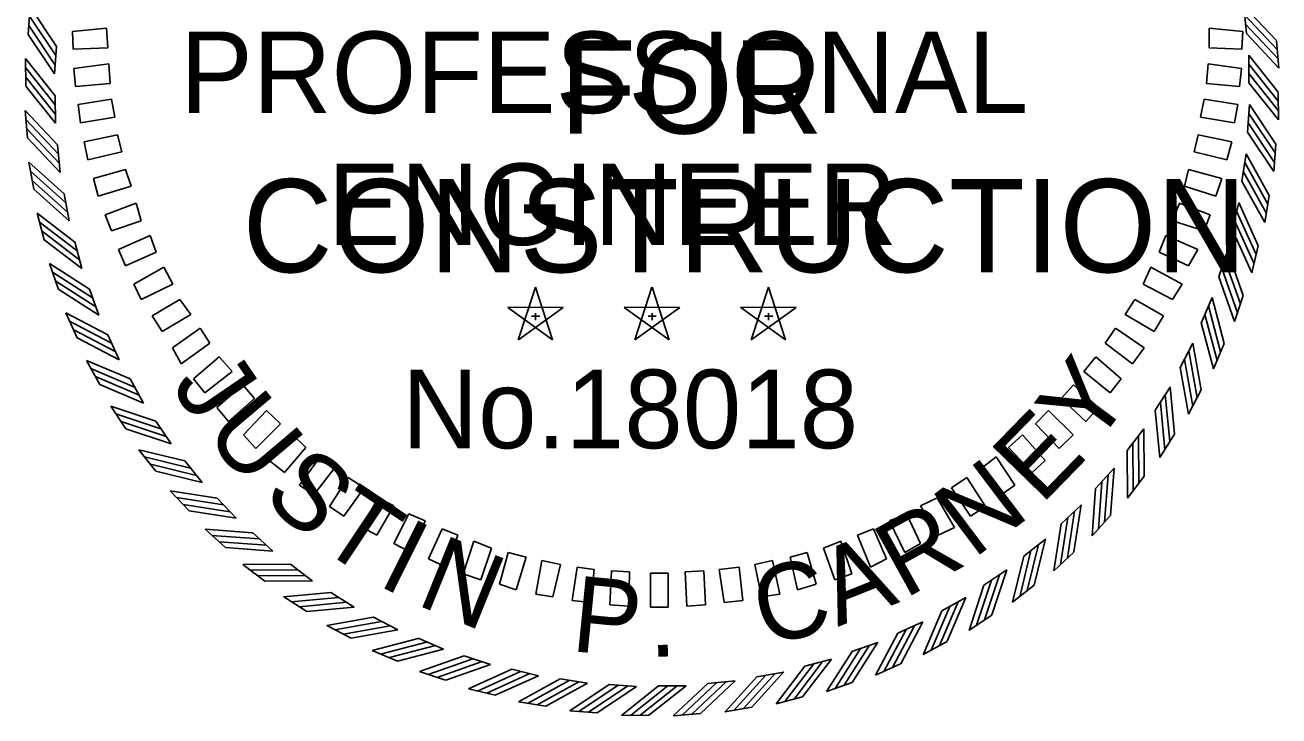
# Model space of a CAD drawing. Extents: x 16 to 1228743, y 11 to 152440.
# Drawn here: x 17.6793 to 17.8515, y 10.8149 to 10.9098 of the extents above; entities that cross this region are included whole.
import ezdxf

# ---------------------------------------------------------------- set-up
doc = ezdxf.new("R2010")
doc.units = 0
doc.layers.add('STAMP_JUSTIN', color=7, linetype='Continuous')
doc.layers.add('STAMP_PRELIM', color=7, linetype='Continuous')

msp = doc.modelspace()

# ---------------------------------------------------------------- linework, layer by layer
at = {"layer": 'STAMP_JUSTIN'}
for p, q in [((17.67974, 10.90855), (17.68001, 10.91231)), ((17.84664, 10.91243), (17.84699, 10.90866)), ((17.85111, 10.90767), (17.85146, 10.90392)), ((17.68336, 10.90312), (17.68364, 10.90689)), ((17.84731, 10.90568), (17.84734, 10.9019)), ((17.67941, 10.90145), (17.67937, 10.90522)), ((17.68347, 10.89634), (17.68343, 10.90012)), ((17.85137, 10.90057), (17.8514, 10.8968)), ((17.84741, 10.8989), (17.84714, 10.89513)), ((17.67966, 10.89435), (17.67932, 10.8981)), ((17.68413, 10.88959), (17.68378, 10.89335)), ((17.85104, 10.89347), (17.85076, 10.88971)), ((17.84696, 10.89213), (17.84637, 10.8884)), ((17.68051, 10.88729), (17.67985, 10.891)), ((17.68535, 10.88292), (17.6847, 10.88664)), ((17.85012, 10.88642), (17.84954, 10.8827)), ((17.84595, 10.88542), (17.84505, 10.88175)), ((17.68193, 10.88033), (17.68097, 10.88397)), ((17.68712, 10.87637), (17.68616, 10.88003)), ((17.84863, 10.87948), (17.84774, 10.87581)), ((17.84439, 10.87883), (17.84319, 10.87524)), ((17.68392, 10.87351), (17.68267, 10.87706)), ((17.68942, 10.86999), (17.68816, 10.87356)), ((17.74939, 10.87381), (17.74703, 10.86658)), ((17.75174, 10.86658), (17.74939, 10.87382)), ((17.76538, 10.87381), (17.76302, 10.86658)), ((17.76773, 10.86658), (17.76539, 10.87382)), ((17.78137, 10.87381), (17.77901, 10.86658)), ((17.78372, 10.86658), (17.78138, 10.87382)), ((17.84657, 10.87268), (17.84538, 10.8691)), ((17.75319, 10.87105), (17.74558, 10.87106)), ((17.74559, 10.87105), (17.75174, 10.86657)), ((17.74704, 10.86658), (17.7532, 10.87105)), ((17.76918, 10.87105), (17.76157, 10.87106)), ((17.76158, 10.87105), (17.76773, 10.86657)), ((17.76303, 10.86658), (17.76919, 10.87105)), ((17.78517, 10.87105), (17.77756, 10.87106)), ((17.77757, 10.87105), (17.78372, 10.86657)), ((17.77902, 10.86658), (17.78518, 10.87105)), ((17.84228, 10.87238), (17.8408, 10.8689)), ((17.68647, 10.86687), (17.68493, 10.87031)), ((17.74885, 10.86983), (17.74998, 10.86983)), ((17.7494, 10.87024), (17.7494, 10.86928)), ((17.76484, 10.86983), (17.76597, 10.86983)), ((17.76539, 10.87024), (17.76539, 10.86928)), ((17.78083, 10.86983), (17.78196, 10.86983)), ((17.78138, 10.87024), (17.78138, 10.86928)), ((17.69224, 10.86383), (17.69069, 10.86727)), ((17.83966, 10.86613), (17.83789, 10.86279)), ((17.84395, 10.86607), (17.84247, 10.8626)), ((17.68956, 10.86047), (17.68774, 10.86377)), ((17.69556, 10.85791), (17.69373, 10.86122)), ((17.83652, 10.86011), (17.83449, 10.85693)), ((17.8408, 10.8597), (17.83903, 10.85637)), ((17.69317, 10.85435), (17.69108, 10.85749)), ((17.69936, 10.85229), (17.69726, 10.85544)), ((17.8329, 10.85438), (17.83061, 10.85137)), ((17.83713, 10.85362), (17.83509, 10.85044)), ((17.69727, 10.84855), (17.69492, 10.8515)), ((17.70361, 10.84701), (17.70126, 10.84997)), ((17.82882, 10.84896), (17.82629, 10.84616)), ((17.83297, 10.84785), (17.83068, 10.84486)), ((17.70183, 10.8431), (17.69925, 10.84585)), ((17.70828, 10.84209), (17.70569, 10.84485)), ((17.82431, 10.8439), (17.82155, 10.84132)), ((17.82835, 10.84245), (17.82582, 10.83966)), ((17.70683, 10.83805), (17.70403, 10.84058)), ((17.71334, 10.83758), (17.71054, 10.84011)), ((17.81939, 10.83923), (17.81643, 10.83688)), ((17.8233, 10.83745), (17.82055, 10.83488)), ((17.71223, 10.83343), (17.70923, 10.83572)), ((17.71875, 10.83349), (17.71575, 10.83579)), ((17.8141, 10.83498), (17.81096, 10.83289)), ((17.71799, 10.82927), (17.71482, 10.8313)), ((17.72449, 10.82987), (17.72131, 10.83191)), ((17.81785, 10.83289), (17.8149, 10.83055)), ((17.80848, 10.83118), (17.80518, 10.82935)), ((17.7305, 10.82674), (17.72716, 10.82851)), ((17.80257, 10.82786), (17.79912, 10.82631)), ((17.81205, 10.82879), (17.80891, 10.8267)), ((17.72408, 10.8256), (17.72075, 10.82736)), ((17.73676, 10.82411), (17.73328, 10.8256)), ((17.7964, 10.82504), (17.79284, 10.82378)), ((17.80592, 10.82518), (17.80262, 10.82336)), ((17.73045, 10.82245), (17.72698, 10.82393)), ((17.7432, 10.82201), (17.73962, 10.8232)), ((17.79002, 10.82274), (17.78637, 10.82178)), ((17.73705, 10.81983), (17.73348, 10.82102)), ((17.7498, 10.82045), (17.74613, 10.82134)), ((17.78348, 10.82097), (17.77976, 10.82032)), ((17.79952, 10.82209), (17.79609, 10.82055)), ((17.75651, 10.81944), (17.75278, 10.82002)), ((17.76328, 10.81898), (17.75951, 10.81926)), ((17.77681, 10.81975), (17.77304, 10.81941)), ((17.79289, 10.81955), (17.78934, 10.81829)), ((17.74386, 10.81777), (17.74019, 10.81866)), ((17.77006, 10.81909), (17.76628, 10.81905)), ((17.78607, 10.81755), (17.78242, 10.81659)), ((17.7508, 10.81627), (17.74708, 10.81686)), ((17.77911, 10.81613), (17.77539, 10.81548)), ((17.75785, 10.81536), (17.75409, 10.81564)), ((17.76495, 10.81503), (17.76118, 10.81499)), ((17.77205, 10.81529), (17.7683, 10.81494))]:
    msp.add_line(p, q, dxfattribs=at)
for points in [[(17.68363, 10.90689), (17.68001, 10.91231)], [(17.84664, 10.91243), (17.85111, 10.90768)], [(17.68353, 10.90563), (17.67991, 10.91106)], [(17.84674, 10.91122), (17.85121, 10.90647)], [(17.68346, 10.90433), (17.67984, 10.90975)], [(17.84689, 10.90992), (17.85136, 10.90517)], [(17.68336, 10.90312), (17.67974, 10.90854)], [(17.84699, 10.90867), (17.85146, 10.90392)], [(17.84731, 10.90568), (17.85136, 10.90058)], [(17.68343, 10.90011), (17.67937, 10.90522)], [(17.68343, 10.89886), (17.67937, 10.90397)], [(17.84731, 10.90447), (17.85136, 10.89936)], [(17.68347, 10.89755), (17.67941, 10.90266)], [(17.84735, 10.90316), (17.85141, 10.89805)], [(17.84735, 10.9019), (17.85141, 10.8968)], [(17.68347, 10.89634), (17.67941, 10.90144)], [(17.84741, 10.8989), (17.85103, 10.89348)], [(17.68378, 10.89335), (17.67932, 10.8981)], [(17.68389, 10.8921), (17.67942, 10.89685)], [(17.84731, 10.89769), (17.85093, 10.89227)], [(17.68404, 10.8908), (17.67957, 10.89555)], [(17.84714, 10.89513), (17.85076, 10.88971)], [(17.84724, 10.89638), (17.85087, 10.89096)], [(17.68414, 10.88959), (17.67967, 10.89434)], [(17.84696, 10.89214), (17.85012, 10.88643)], [(17.68469, 10.88664), (17.67985, 10.89101)], [(17.84676, 10.89094), (17.84992, 10.88523)], [(17.6849, 10.8854), (17.68006, 10.88977)], [(17.68516, 10.88411), (17.68031, 10.88848)], [(17.84638, 10.8884), (17.84954, 10.8827)], [(17.84658, 10.88964), (17.84975, 10.88394)], [(17.68536, 10.88292), (17.68051, 10.88729)], [(17.84595, 10.88543), (17.84863, 10.87948)], [(17.68616, 10.88002), (17.68097, 10.88398)], [(17.84537, 10.88297), (17.84805, 10.87703)], [(17.84565, 10.88425), (17.84833, 10.87831)], [(17.68646, 10.8788), (17.68128, 10.88276)], [(17.68683, 10.87755), (17.68164, 10.8815)], [(17.84506, 10.88176), (17.84774, 10.87581)], [(17.68712, 10.87637), (17.68194, 10.88032)], [(17.84438, 10.87883), (17.84656, 10.87268)], [(17.68816, 10.87355), (17.68266, 10.87706)], [(17.8436, 10.87643), (17.84578, 10.87028)], [(17.84399, 10.87768), (17.84617, 10.87154)], [(17.68857, 10.87236), (17.68307, 10.87588)], [(17.68903, 10.87114), (17.68353, 10.87465)], [(17.8432, 10.87524), (17.84538, 10.8691)], [(17.68943, 10.86999), (17.68393, 10.8735)], [(17.8418, 10.87127), (17.84346, 10.86496)], [(17.84228, 10.87238), (17.84395, 10.86608)], [(17.69069, 10.86727), (17.68492, 10.87031)], [(17.6912, 10.86612), (17.68543, 10.86916)], [(17.84131, 10.87006), (17.84297, 10.86375)], [(17.69176, 10.86494), (17.68599, 10.86798)], [(17.8408, 10.86891), (17.84247, 10.8626)], [(17.69225, 10.86382), (17.68648, 10.86687)], [(17.83966, 10.86613), (17.8408, 10.85971)], [(17.83908, 10.86506), (17.84022, 10.85864)], [(17.69373, 10.86121), (17.68773, 10.86377)], [(17.69433, 10.86011), (17.68833, 10.86267)], [(17.83789, 10.86279), (17.83903, 10.85637)], [(17.83849, 10.86389), (17.83963, 10.85747)], [(17.69499, 10.85898), (17.68899, 10.86154)], [(17.69557, 10.85791), (17.68957, 10.86047)], [(17.83586, 10.8591), (17.83646, 10.85261)], [(17.83652, 10.86012), (17.83713, 10.85362)], [(17.69726, 10.85543), (17.69107, 10.85749)], [(17.83518, 10.85798), (17.83578, 10.85149)], [(17.69795, 10.85438), (17.69176, 10.85644)], [(17.6987, 10.85331), (17.69251, 10.85536)], [(17.83449, 10.85693), (17.83509, 10.85044)], [(17.69936, 10.85229), (17.69317, 10.85435)], [(17.8329, 10.85438), (17.83297, 10.84786)], [(17.83139, 10.85237), (17.83145, 10.84584)], [(17.83216, 10.85342), (17.83222, 10.8469)], [(17.70126, 10.84996), (17.69492, 10.8515)], [(17.70203, 10.84897), (17.69569, 10.85051)], [(17.83061, 10.85138), (17.83068, 10.84485)], [(17.70287, 10.84796), (17.69653, 10.8495)], [(17.70361, 10.84701), (17.69727, 10.84854)], [(17.82882, 10.84897), (17.82835, 10.84246)], [(17.82714, 10.84708), (17.82667, 10.84058)], [(17.828, 10.84807), (17.82753, 10.84157)], [(17.70569, 10.84484), (17.69925, 10.84585)], [(17.82629, 10.84616), (17.82582, 10.83965)], [(17.70654, 10.84392), (17.7001, 10.84493)], [(17.70746, 10.84298), (17.70102, 10.84399)], [(17.82431, 10.84391), (17.8233, 10.83746)], [(17.70828, 10.84209), (17.70184, 10.8431)], [(17.82248, 10.84217), (17.82147, 10.83572)], [(17.82341, 10.84308), (17.82241, 10.83664)], [(17.71054, 10.8401), (17.70403, 10.84058)], [(17.82155, 10.84132), (17.82055, 10.83487)], [(17.71146, 10.83925), (17.70495, 10.83973)], [(17.71245, 10.8384), (17.70595, 10.83887)], [(17.81843, 10.83849), (17.8169, 10.83215)], [(17.81939, 10.83924), (17.81785, 10.8329)], [(17.71334, 10.83758), (17.70684, 10.83805)], [(17.81643, 10.83688), (17.8149, 10.83054)], [(17.81742, 10.83765), (17.81589, 10.83131)], [(17.71575, 10.83578), (17.70923, 10.83572)], [(17.71674, 10.83501), (17.71022, 10.83495)], [(17.8141, 10.83499), (17.81205, 10.8288)], [(17.7178, 10.83424), (17.71128, 10.83417)], [(17.71876, 10.83349), (17.71224, 10.83343)], [(17.81202, 10.83357), (17.80996, 10.82738)], [(17.81309, 10.83432), (17.81103, 10.82813)], [(17.72131, 10.83191), (17.71481, 10.8313)], [(17.81096, 10.83289), (17.80891, 10.82669)], [(17.72236, 10.83122), (17.71587, 10.83062)], [(17.72348, 10.83054), (17.71698, 10.82993)], [(17.72449, 10.82987), (17.718, 10.82927)], [(17.80629, 10.82995), (17.80373, 10.82395)], [(17.80742, 10.83061), (17.80486, 10.82461)], [(17.80849, 10.83119), (17.80593, 10.82519)], [(17.72717, 10.8285), (17.72074, 10.82736)], [(17.72827, 10.82791), (17.72185, 10.82677)], [(17.80257, 10.82787), (17.79953, 10.8221)], [(17.80518, 10.82935), (17.80262, 10.82335)], [(17.72944, 10.82732), (17.72302, 10.82618)], [(17.73051, 10.82674), (17.72409, 10.8256)], [(17.79913, 10.82631), (17.79608, 10.82054)], [(17.80028, 10.82682), (17.79723, 10.82105)], [(17.80146, 10.82738), (17.79842, 10.82161)], [(17.73328, 10.82559), (17.72698, 10.82393)], [(17.73443, 10.82509), (17.72813, 10.82342)], [(17.73565, 10.8246), (17.72934, 10.82294)], [(17.79526, 10.82465), (17.79175, 10.81916)], [(17.79641, 10.82505), (17.79289, 10.81955)], [(17.73676, 10.82411), (17.73045, 10.82245)], [(17.73962, 10.8232), (17.73347, 10.82102)], [(17.74081, 10.82279), (17.73466, 10.82061)], [(17.79003, 10.82275), (17.78607, 10.81756)], [(17.79285, 10.82378), (17.78933, 10.81828)], [(17.79403, 10.82419), (17.79052, 10.81869)], [(17.74206, 10.82241), (17.73591, 10.82023)], [(17.74321, 10.82201), (17.73706, 10.81983)], [(17.74614, 10.82134), (17.74019, 10.81866)], [(17.74735, 10.82103), (17.74141, 10.81835)], [(17.78348, 10.82098), (17.77911, 10.81613)], [(17.78637, 10.82178), (17.78242, 10.81659)], [(17.78759, 10.82209), (17.78364, 10.8169)], [(17.78885, 10.82245), (17.7849, 10.81726)], [(17.74863, 10.82075), (17.74269, 10.81807)], [(17.74981, 10.82045), (17.74386, 10.81777)], [(17.75278, 10.82002), (17.74707, 10.81686)], [(17.75402, 10.81981), (17.74831, 10.81665)], [(17.75532, 10.81964), (17.74961, 10.81648)], [(17.75651, 10.81944), (17.75081, 10.81628)], [(17.75951, 10.81926), (17.75409, 10.81563)], [(17.77305, 10.8194), (17.76829, 10.81494)], [(17.7743, 10.81951), (17.76954, 10.81504)], [(17.7756, 10.81966), (17.77085, 10.81519)], [(17.77681, 10.81976), (17.77206, 10.81529)], [(17.77976, 10.82032), (17.77539, 10.81547)], [(17.781, 10.82052), (17.77663, 10.81568)], [(17.78228, 10.82078), (17.77791, 10.81593)], [(17.76076, 10.81915), (17.75534, 10.81553)], [(17.76207, 10.81909), (17.75665, 10.81546)], [(17.76328, 10.81899), (17.75786, 10.81536)], [(17.76628, 10.81905), (17.76118, 10.81499)], [(17.76754, 10.81905), (17.76243, 10.81499)], [(17.76885, 10.81909), (17.76374, 10.81503)], [(17.77006, 10.81909), (17.76495, 10.81503)]]:
    msp.add_lwpolyline(points, dxfattribs=at)
at = {"layer": 'STAMP_PRELIM'}
for p, q in [((17.68581, 10.90893), (17.6905, 10.90937)), ((17.68594, 10.9065), (17.68581, 10.90893)), ((17.6905, 10.90937), (17.69069, 10.90668)), ((17.84187, 10.90937), (17.8465, 10.90893)), ((17.84187, 10.90668), (17.84187, 10.90937)), ((17.8465, 10.90893), (17.84637, 10.9065)), ((17.69069, 10.90668), (17.68594, 10.9065)), ((17.84637, 10.9065), (17.84187, 10.90668)), ((17.686, 10.90387), (17.69081, 10.9045)), ((17.68625, 10.90137), (17.686, 10.90387)), ((17.69081, 10.9045), (17.691, 10.9018)), ((17.8415, 10.9018), (17.84175, 10.9045)), ((17.84175, 10.9045), (17.84631, 10.90387)), ((17.84631, 10.90387), (17.84606, 10.90137)), ((17.691, 10.9018), (17.68625, 10.90137)), ((17.84606, 10.90137), (17.8415, 10.9018)), ((17.68662, 10.89893), (17.69119, 10.89962)), ((17.68694, 10.89637), (17.68662, 10.89893)), ((17.69119, 10.89962), (17.69162, 10.89718)), ((17.84069, 10.89718), (17.84119, 10.89962)), ((17.84119, 10.89962), (17.84581, 10.89893)), ((17.84581, 10.89893), (17.84537, 10.89637)), ((17.69162, 10.89718), (17.68694, 10.89637)), ((17.84537, 10.89637), (17.84069, 10.89718)), ((17.68744, 10.8938), (17.692, 10.89475)), ((17.68794, 10.8913), (17.68744, 10.8938)), ((17.692, 10.89475), (17.69262, 10.89243)), ((17.83981, 10.89243), (17.84037, 10.89475)), ((17.84037, 10.89475), (17.845, 10.8938)), ((17.845, 10.8938), (17.84431, 10.8913)), ((17.69262, 10.89243), (17.68794, 10.8913)), ((17.84431, 10.8913), (17.83981, 10.89243)), ((17.68869, 10.88875), (17.69312, 10.89)), ((17.69312, 10.89), (17.69387, 10.88768)), ((17.83906, 10.89), (17.8385, 10.88768)), ((17.84362, 10.88875), (17.83906, 10.89)), ((17.68937, 10.8863), (17.68869, 10.88875)), ((17.84281, 10.8863), (17.84362, 10.88875)), ((17.69387, 10.88768), (17.68937, 10.8863)), ((17.8385, 10.88768), (17.84281, 10.8863)), ((17.69031, 10.88375), (17.69456, 10.88537)), ((17.69456, 10.88537), (17.69525, 10.88293)), ((17.83781, 10.88537), (17.83687, 10.88293)), ((17.842, 10.88375), (17.83781, 10.88537)), ((17.69119, 10.88155), (17.69031, 10.88375)), ((17.69525, 10.88293), (17.69119, 10.88155)), ((17.83687, 10.88293), (17.84119, 10.88155)), ((17.84119, 10.88155), (17.842, 10.88375)), ((17.6965, 10.88093), (17.69212, 10.879)), ((17.69731, 10.87862), (17.6965, 10.88093)), ((17.83594, 10.88093), (17.835, 10.87862)), ((17.84031, 10.879), (17.83594, 10.88093)), ((17.69212, 10.879), (17.69312, 10.87675)), ((17.69312, 10.87675), (17.69731, 10.87862)), ((17.835, 10.87862), (17.83906, 10.87675)), ((17.83906, 10.87675), (17.84031, 10.879)), ((17.69837, 10.87655), (17.69425, 10.87425)), ((17.69962, 10.87425), (17.69837, 10.87655)), ((17.83281, 10.87425), (17.83387, 10.87655)), ((17.83387, 10.87655), (17.83819, 10.87425)), ((17.69425, 10.87425), (17.69525, 10.87212)), ((17.69525, 10.87212), (17.69962, 10.87425)), ((17.83687, 10.87212), (17.83281, 10.87425)), ((17.83819, 10.87425), (17.83687, 10.87212)), ((17.69675, 10.86987), (17.70056, 10.87212)), ((17.70056, 10.87212), (17.70206, 10.87005)), ((17.83169, 10.87212), (17.83037, 10.87005)), ((17.83562, 10.86987), (17.83169, 10.87212)), ((17.69812, 10.86775), (17.69675, 10.86987)), ((17.70206, 10.87005), (17.69812, 10.86775)), ((17.83037, 10.87005), (17.83431, 10.86775)), ((17.83431, 10.86775), (17.83562, 10.86987)), ((17.70337, 10.86818), (17.69956, 10.8655)), ((17.70469, 10.86612), (17.70337, 10.86818)), ((17.82762, 10.86612), (17.829, 10.86818)), ((17.829, 10.86818), (17.83294, 10.8655)), ((17.70075, 10.8633), (17.70469, 10.86612)), ((17.83137, 10.8633), (17.82762, 10.86612)), ((17.69956, 10.8655), (17.70075, 10.8633)), ((17.70244, 10.86125), (17.70594, 10.86425)), ((17.70594, 10.86425), (17.70775, 10.86225)), ((17.82469, 10.86225), (17.82631, 10.86425)), ((17.82631, 10.86425), (17.82981, 10.86125)), ((17.83294, 10.8655), (17.83137, 10.8633)), ((17.70775, 10.86225), (17.704, 10.8593)), ((17.82831, 10.8593), (17.82469, 10.86225)), ((17.704, 10.8593), (17.70244, 10.86125)), ((17.82981, 10.86125), (17.82831, 10.8593)), ((17.70919, 10.86043), (17.70562, 10.8573)), ((17.71081, 10.85855), (17.70919, 10.86043)), ((17.82325, 10.86043), (17.82156, 10.85855)), ((17.82669, 10.8573), (17.82325, 10.86043)), ((17.70562, 10.8573), (17.70725, 10.85537)), ((17.70725, 10.85537), (17.71081, 10.85855)), ((17.82156, 10.85855), (17.82494, 10.85537)), ((17.82494, 10.85537), (17.82669, 10.8573)), ((17.70931, 10.85355), (17.71244, 10.85687)), ((17.71244, 10.85687), (17.71437, 10.85505)), ((17.81981, 10.85687), (17.81806, 10.85505)), ((17.82319, 10.85355), (17.81981, 10.85687)), ((17.71437, 10.85505), (17.711, 10.85168)), ((17.81806, 10.85505), (17.82131, 10.85168)), ((17.711, 10.85168), (17.70931, 10.85355)), ((17.71606, 10.85355), (17.71281, 10.85)), ((17.71787, 10.8518), (17.71606, 10.85355)), ((17.81625, 10.85355), (17.81431, 10.8518)), ((17.81937, 10.85), (17.81625, 10.85355)), ((17.82131, 10.85168), (17.82319, 10.85355)), ((17.71494, 10.84837), (17.71787, 10.8518)), ((17.717, 10.84662), (17.71981, 10.8505)), ((17.71981, 10.8505), (17.72175, 10.84893)), ((17.81262, 10.8505), (17.81056, 10.84893)), ((17.81519, 10.84662), (17.81262, 10.8505)), ((17.81431, 10.8518), (17.81756, 10.84837)), ((17.71281, 10.85), (17.71494, 10.84837)), ((17.72175, 10.84893), (17.71894, 10.8453)), ((17.81056, 10.84893), (17.81331, 10.8453)), ((17.81756, 10.84837), (17.81937, 10.85)), ((17.72112, 10.84368), (17.72369, 10.84768)), ((17.72369, 10.84768), (17.72587, 10.84625)), ((17.80862, 10.84768), (17.8065, 10.84625)), ((17.81119, 10.84368), (17.80862, 10.84768)), ((17.71894, 10.8453), (17.717, 10.84662)), ((17.72587, 10.84625), (17.72306, 10.84237)), ((17.8065, 10.84625), (17.80912, 10.84237)), ((17.81331, 10.8453), (17.81519, 10.84662)), ((17.72306, 10.84237), (17.72112, 10.84368)), ((17.72775, 10.84487), (17.72562, 10.8408)), ((17.72762, 10.83975), (17.72994, 10.8438)), ((17.72994, 10.8438), (17.72775, 10.84487)), ((17.80456, 10.84487), (17.80225, 10.8438)), ((17.80225, 10.8438), (17.80469, 10.83975)), ((17.80694, 10.8408), (17.80456, 10.84487)), ((17.80912, 10.84237), (17.81119, 10.84368)), ((17.72994, 10.83862), (17.732, 10.84268)), ((17.732, 10.84268), (17.73425, 10.84175)), ((17.73425, 10.84175), (17.73231, 10.83737)), ((17.798, 10.84175), (17.80031, 10.84268)), ((17.80012, 10.83737), (17.798, 10.84175)), ((17.80031, 10.84268), (17.80225, 10.83862)), ((17.72562, 10.8408), (17.72762, 10.83975)), ((17.73656, 10.84062), (17.73469, 10.8365)), ((17.73875, 10.83975), (17.73656, 10.84062)), ((17.79581, 10.84062), (17.79362, 10.83975)), ((17.79756, 10.8365), (17.79581, 10.84062)), ((17.80469, 10.83975), (17.80694, 10.8408)), ((17.73231, 10.83737), (17.72994, 10.83862)), ((17.73712, 10.83537), (17.73875, 10.83975)), ((17.73944, 10.83443), (17.74094, 10.83893)), ((17.74094, 10.83893), (17.74337, 10.838)), ((17.78894, 10.838), (17.79131, 10.83893)), ((17.79131, 10.83893), (17.79281, 10.83443)), ((17.79362, 10.83975), (17.79537, 10.83537)), ((17.80225, 10.83862), (17.80012, 10.83737)), ((17.73469, 10.8365), (17.73712, 10.83537)), ((17.74337, 10.838), (17.74187, 10.83362)), ((17.74444, 10.83305), (17.74562, 10.83737)), ((17.74562, 10.83737), (17.74812, 10.83675)), ((17.74812, 10.83675), (17.74675, 10.83225)), ((17.78669, 10.83737), (17.78437, 10.83675)), ((17.78437, 10.83675), (17.78537, 10.83225)), ((17.78794, 10.83305), (17.78669, 10.83737)), ((17.7905, 10.83362), (17.78894, 10.838)), ((17.79537, 10.83537), (17.79756, 10.8365)), ((17.75025, 10.8363), (17.74944, 10.83168)), ((17.75281, 10.83575), (17.75025, 10.8363)), ((17.75175, 10.8313), (17.75281, 10.83575)), ((17.75444, 10.8308), (17.75512, 10.83537)), ((17.75512, 10.83537), (17.75744, 10.83505)), ((17.75744, 10.83505), (17.757, 10.8305)), ((17.75981, 10.83487), (17.75962, 10.83018)), ((17.76231, 10.83475), (17.75981, 10.83487)), ((17.76219, 10.83), (17.76231, 10.83475)), ((17.76994, 10.83475), (17.7725, 10.83487)), ((17.77019, 10.83), (17.76994, 10.83475)), ((17.7725, 10.83487), (17.77275, 10.83018)), ((17.77737, 10.83537), (17.77462, 10.83505)), ((17.77462, 10.83505), (17.77531, 10.8305)), ((17.77787, 10.8308), (17.77737, 10.83537)), ((17.78194, 10.8363), (17.7795, 10.83575)), ((17.7795, 10.83575), (17.78044, 10.8313)), ((17.78294, 10.83168), (17.78194, 10.8363)), ((17.74187, 10.83362), (17.73944, 10.83443)), ((17.74675, 10.83225), (17.74444, 10.83305)), ((17.76519, 10.83455), (17.76519, 10.82987)), ((17.76762, 10.83455), (17.76519, 10.83455)), ((17.76762, 10.82987), (17.76762, 10.83455)), ((17.78537, 10.83225), (17.78794, 10.83305)), ((17.79281, 10.83443), (17.7905, 10.83362)), ((17.74944, 10.83168), (17.75175, 10.8313)), ((17.78044, 10.8313), (17.78294, 10.83168)), ((17.757, 10.8305), (17.75444, 10.8308)), ((17.75962, 10.83018), (17.76219, 10.83)), ((17.76519, 10.82987), (17.76762, 10.82987)), ((17.77275, 10.83018), (17.77019, 10.83)), ((17.77531, 10.8305), (17.77787, 10.8308))]:
    msp.add_line(p, q, dxfattribs=at)

# ---------------------------------------------------------------- texts
at = {"layer": 'STAMP_JUSTIN'}
for s, height, p in [('PROFESSIONAL', 0.0111936, (17.7006, 10.89773)), ('ENGINEER', 0.011194, (17.72085, 10.87961)), ('No.18018', 0.010794, (17.73109, 10.8517))]:
    msp.add_text(s, height=height, dxfattribs=at).set_placement(p)
for s, rotation, p in [('Y', 53.4433, (17.82597, 10.85141)), ('J', 304.3679, (17.69921, 10.8603)), ('U', 310.2047, (17.70369, 10.85374)), ('E', 45.7825, (17.81882, 10.84382)), ('S', 318.9599, (17.71161, 10.84484)), ('N', 37.0272, (17.8095, 10.83641)), ('T', 326.256, (17.71918, 10.83842)), ('R', 29.0016, (17.80005, 10.83094)), ('I', 333.552, (17.7275, 10.83301)), ('N', 337.9296, (17.7328, 10.83029)), ('A', 21.7056, (17.79088, 10.82715)), ('C', 14.0448, (17.78081, 10.82446)), ('P', 354.3456, (17.75413, 10.82386)), ('.', 2.3712, (17.76501, 10.823))]:
    msp.add_text(s, height=0.01042, rotation=rotation, dxfattribs=at).set_placement(p)
at = {"layer": 'STAMP_PRELIM'}
for s, height, p in [('FOR', 0.012794, (17.75274, 10.89492)), ('CONSTRUCTION', 0.0127938, (17.70918, 10.87587))]:
    msp.add_text(s, height=height, dxfattribs=at).set_placement(p)

doc.saveas('drawing.dxf')
